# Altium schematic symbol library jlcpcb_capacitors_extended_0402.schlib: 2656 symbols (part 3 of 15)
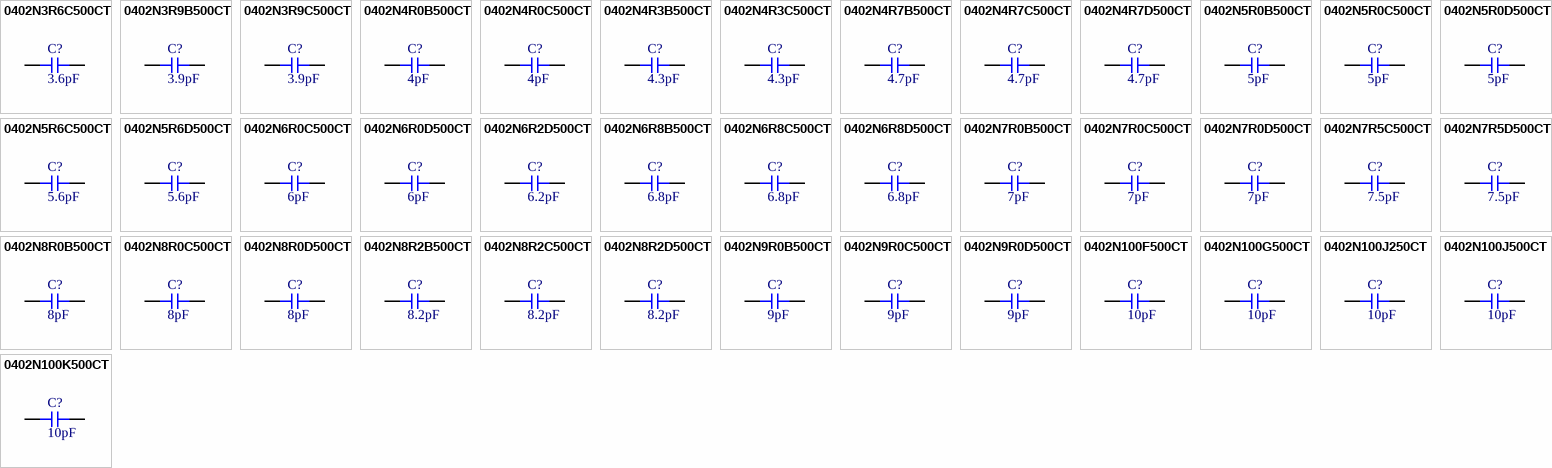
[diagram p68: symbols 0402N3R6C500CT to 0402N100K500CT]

## 0402N100J250CT
designator C?  Capacitance: 10pF  (hidden comment: *)
Capacitor, Ceramic (MLCC), 10pF, ±5%, 25V, NP0, ±5%, SMD 0402; Manufacturer: Walsin Tech Corp; Manufacturer Part Number: 0402N100J250CT
footprint CAP-0402 (0402 (1005M) Capacitor)
pins: 1, 2

## 0402N100J500CT
designator C?  Capacitance: 10pF  (hidden comment: *)
Capacitor, Ceramic (MLCC), 10pF, ±5%, 50V, NP0, ±5%, SMD 0402; Manufacturer: Walsin Tech Corp; Manufacturer Part Number: 0402N100J500CT
footprint CAP-0402 (0402 (1005M) Capacitor)
pins: 1, 2

## 0402N100K500CT
designator C?  Capacitance: 10pF  (hidden comment: *)
Capacitor, Ceramic (MLCC), 10pF, ±10%, 50V, NP0, ±10%, SMD 0402; Manufacturer: Walsin Tech Corp; Manufacturer Part Number: 0402N100K500CT
footprint CAP-0402 (0402 (1005M) Capacitor)
pins: 1, 2

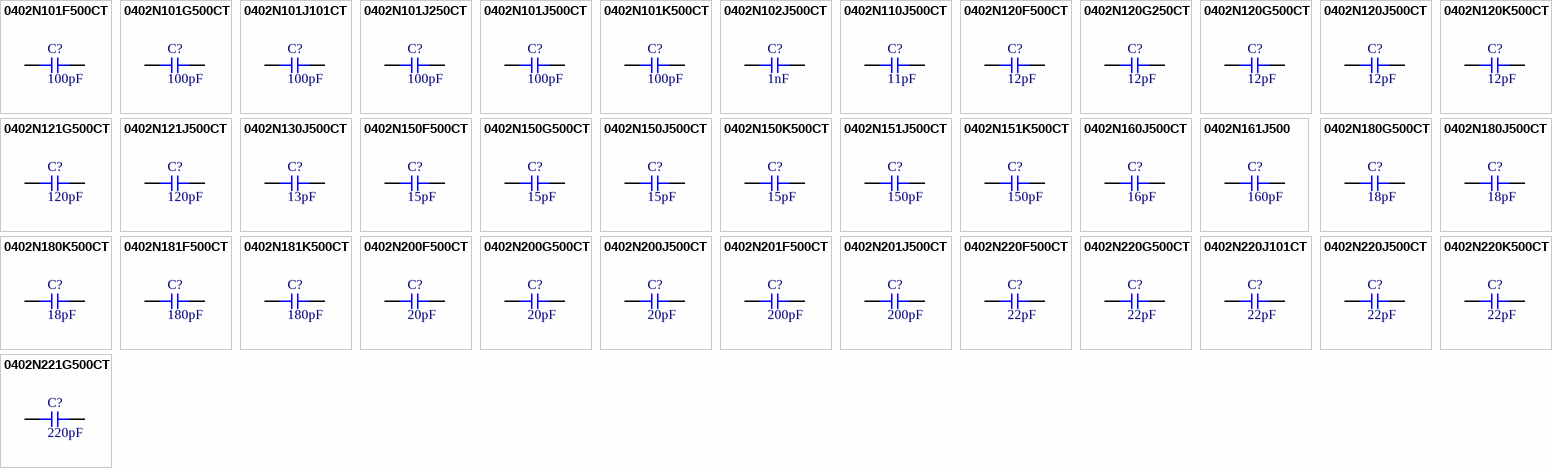
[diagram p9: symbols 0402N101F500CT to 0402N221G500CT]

## 0402N101F500CT
designator C?  Capacitance: 100pF  (hidden comment: *)
Capacitor, Ceramic (MLCC), 100pF, ±1%, 50V, NP0, ±1%, SMD 0402; Manufacturer: Walsin Tech Corp; Manufacturer Part Number: 0402N101F500CT
footprint CAP-0402 (0402 (1005M) Capacitor)
pins: 1, 2

## 0402N101G500CT
designator C?  Capacitance: 100pF  (hidden comment: *)
Capacitor, Ceramic (MLCC), 100pF, ±2%, 50V, NP0, ±2%, SMD 0402; Manufacturer: Walsin Tech Corp; Manufacturer Part Number: 0402N101G500CT
footprint CAP-0402 (0402 (1005M) Capacitor)
pins: 1, 2

## 0402N101J101CT
designator C?  Capacitance: 100pF  (hidden comment: *)
Capacitor, Ceramic (MLCC), 100pF, ±5%, 100V, NP0, ±5%, SMD 0402; Manufacturer: Walsin Tech Corp; Manufacturer Part Number: 0402N101J101CT
footprint CAP-0402 (0402 (1005M) Capacitor)
pins: 1, 2

## 0402N101J250CT
designator C?  Capacitance: 100pF  (hidden comment: *)
Capacitor, Ceramic (MLCC), 100pF, ±5%, 25V, NP0, ±5%, SMD 0402; Manufacturer: Walsin Tech Corp; Manufacturer Part Number: 0402N101J250CT
footprint CAP-0402 (0402 (1005M) Capacitor)
pins: 1, 2

## 0402N101J500CT
designator C?  Capacitance: 100pF  (hidden comment: *)
Capacitor, Ceramic (MLCC), 100pF, ±5%, 50V, NP0, ±5%, SMD 0402; Manufacturer: Walsin Tech Corp; Manufacturer Part Number: 0402N101J500CT
footprint CAP-0402 (0402 (1005M) Capacitor)
pins: 1, 2

## 0402N101K500CT
designator C?  Capacitance: 100pF  (hidden comment: *)
Capacitor, Ceramic (MLCC), 100pF, ±10%, 50V, NP0, ±10%, SMD 0402; Manufacturer: Walsin Tech Corp; Manufacturer Part Number: 0402N101K500CT
footprint CAP-0402 (0402 (1005M) Capacitor)
pins: 1, 2

## 0402N102J500CT
designator C?  Capacitance: 1nF  (hidden comment: *)
Capacitor, Ceramic (MLCC), 1nF, ±5%, 50V, NP0, ±5%, SMD 0402; Manufacturer: Walsin Tech Corp; Manufacturer Part Number: 0402N102J500CT
footprint CAP-0402 (0402 (1005M) Capacitor)
pins: 1, 2

## 0402N110J500CT
designator C?  Capacitance: 11pF  (hidden comment: *)
Capacitor, Ceramic (MLCC), 11pF, ±5%, 50V, NP0, ±5%, SMD 0402; Manufacturer: Walsin Tech Corp; Manufacturer Part Number: 0402N110J500CT
footprint CAP-0402 (0402 (1005M) Capacitor)
pins: 1, 2

## 0402N120F500CT
designator C?  Capacitance: 12pF  (hidden comment: *)
Capacitor, Ceramic (MLCC), 12pF, ±1%, 50V, NP0, ±1%, SMD 0402; Manufacturer: Walsin Tech Corp; Manufacturer Part Number: 0402N120F500CT
footprint CAP-0402 (0402 (1005M) Capacitor)
pins: 1, 2

## 0402N120G250CT
designator C?  Capacitance: 12pF  (hidden comment: *)
Capacitor, Ceramic (MLCC), 12pF, ±2%, 25V, NP0, ±2%, SMD 0402; Manufacturer: Walsin Tech Corp; Manufacturer Part Number: 0402N120G250CT
footprint CAP-0402 (0402 (1005M) Capacitor)
pins: 1, 2

## 0402N120G500CT
designator C?  Capacitance: 12pF  (hidden comment: *)
Capacitor, Ceramic (MLCC), 12pF, ±2%, 50V, NP0, ±2%, SMD 0402; Manufacturer: Walsin Tech Corp; Manufacturer Part Number: 0402N120G500CT
footprint CAP-0402 (0402 (1005M) Capacitor)
pins: 1, 2

## 0402N120J500CT
designator C?  Capacitance: 12pF  (hidden comment: *)
Capacitor, Ceramic (MLCC), 12pF, ±5%, 50V, NP0, ±5%, SMD 0402; Manufacturer: Walsin Tech Corp; Manufacturer Part Number: 0402N120J500CT
footprint CAP-0402 (0402 (1005M) Capacitor)
pins: 1, 2

## 0402N120K500CT
designator C?  Capacitance: 12pF  (hidden comment: *)
Capacitor, Ceramic (MLCC), 12pF, ±10%, 50V, NP0, ±10%, SMD 0402; Manufacturer: Walsin Tech Corp; Manufacturer Part Number: 0402N120K500CT
footprint CAP-0402 (0402 (1005M) Capacitor)
pins: 1, 2

## 0402N121G500CT
designator C?  Capacitance: 120pF  (hidden comment: *)
Capacitor, Ceramic (MLCC), 120pF, ±2%, 50V, NP0, ±2%, SMD 0402; Manufacturer: Walsin Tech Corp; Manufacturer Part Number: 0402N121G500CT
footprint CAP-0402 (0402 (1005M) Capacitor)
pins: 1, 2

## 0402N121J500CT
designator C?  Capacitance: 120pF  (hidden comment: *)
Capacitor, Ceramic (MLCC), 120pF, ±5%, 50V, NP0, ±5%, SMD 0402; Manufacturer: Walsin Tech Corp; Manufacturer Part Number: 0402N121J500CT
footprint CAP-0402 (0402 (1005M) Capacitor)
pins: 1, 2

## 0402N130J500CT
designator C?  Capacitance: 13pF  (hidden comment: *)
Capacitor, Ceramic (MLCC), 13pF, ±5%, 50V, NP0, ±5%, SMD 0402; Manufacturer: Walsin Tech Corp; Manufacturer Part Number: 0402N130J500CT
footprint CAP-0402 (0402 (1005M) Capacitor)
pins: 1, 2

## 0402N150F500CT
designator C?  Capacitance: 15pF  (hidden comment: *)
Capacitor, Ceramic (MLCC), 15pF, ±1%, 50V, NP0, ±1%, SMD 0402; Manufacturer: Walsin Tech Corp; Manufacturer Part Number: 0402N150F500CT
footprint CAP-0402 (0402 (1005M) Capacitor)
pins: 1, 2

## 0402N150G500CT
designator C?  Capacitance: 15pF  (hidden comment: *)
Capacitor, Ceramic (MLCC), 15pF, ±2%, 50V, NP0, ±2%, SMD 0402; Manufacturer: Walsin Tech Corp; Manufacturer Part Number: 0402N150G500CT
footprint CAP-0402 (0402 (1005M) Capacitor)
pins: 1, 2

## 0402N150J500CT
designator C?  Capacitance: 15pF  (hidden comment: *)
Capacitor, Ceramic (MLCC), 15pF, ±5%, 50V, NP0, ±5%, SMD 0402; Manufacturer: Walsin Tech Corp; Manufacturer Part Number: 0402N150J500CT
footprint CAP-0402 (0402 (1005M) Capacitor)
pins: 1, 2

## 0402N150K500CT
designator C?  Capacitance: 15pF  (hidden comment: *)
Capacitor, Ceramic (MLCC), 15pF, ±10%, 50V, NP0, ±10%, SMD 0402; Manufacturer: Walsin Tech Corp; Manufacturer Part Number: 0402N150K500CT
footprint CAP-0402 (0402 (1005M) Capacitor)
pins: 1, 2

## 0402N151J500CT
designator C?  Capacitance: 150pF  (hidden comment: *)
Capacitor, Ceramic (MLCC), 150pF, ±5%, 50V, NP0, ±5%, SMD 0402; Manufacturer: Walsin Tech Corp; Manufacturer Part Number: 0402N151J500CT
footprint CAP-0402 (0402 (1005M) Capacitor)
pins: 1, 2

## 0402N151K500CT
designator C?  Capacitance: 150pF  (hidden comment: *)
Capacitor, Ceramic (MLCC), 150pF, ±10%, 50V, NP0, ±10%, SMD 0402; Manufacturer: Walsin Tech Corp; Manufacturer Part Number: 0402N151K500CT
footprint CAP-0402 (0402 (1005M) Capacitor)
pins: 1, 2

## 0402N160J500CT
designator C?  Capacitance: 16pF  (hidden comment: *)
Capacitor, Ceramic (MLCC), 16pF, ±5%, 50V, NP0, ±5%, SMD 0402; Manufacturer: Walsin Tech Corp; Manufacturer Part Number: 0402N160J500CT
footprint CAP-0402 (0402 (1005M) Capacitor)
pins: 1, 2

## 0402N161J500
designator C?  Capacitance: 160pF  (hidden comment: *)
Capacitor, Ceramic (MLCC), 160pF, ±5%, 50V, NP0, ±5%, SMD 0402; Manufacturer: Walsin Tech Corp; Manufacturer Part Number: 0402N161J500
footprint CAP-0402 (0402 (1005M) Capacitor)
pins: 1, 2

## 0402N180G500CT
designator C?  Capacitance: 18pF  (hidden comment: *)
Capacitor, Ceramic (MLCC), 18pF, ±2%, 50V, NP0, ±2%, SMD 0402; Manufacturer: Walsin Tech Corp; Manufacturer Part Number: 0402N180G500CT
footprint CAP-0402 (0402 (1005M) Capacitor)
pins: 1, 2

## 0402N180J500CT
designator C?  Capacitance: 18pF  (hidden comment: *)
Capacitor, Ceramic (MLCC), 18pF, ±5%, 50V, NP0, ±5%, SMD 0402; Manufacturer: Walsin Tech Corp; Manufacturer Part Number: 0402N180J500CT
footprint CAP-0402 (0402 (1005M) Capacitor)
pins: 1, 2

## 0402N180K500CT
designator C?  Capacitance: 18pF  (hidden comment: *)
Capacitor, Ceramic (MLCC), 18pF, ±10%, 50V, NP0, ±10%, SMD 0402; Manufacturer: Walsin Tech Corp; Manufacturer Part Number: 0402N180K500CT
footprint CAP-0402 (0402 (1005M) Capacitor)
pins: 1, 2

## 0402N181F500CT
designator C?  Capacitance: 180pF  (hidden comment: *)
Capacitor, Ceramic (MLCC), 180pF, ±1%, 50V, NP0, ±1%, SMD 0402; Manufacturer: Walsin Tech Corp; Manufacturer Part Number: 0402N181F500CT
footprint CAP-0402 (0402 (1005M) Capacitor)
pins: 1, 2

## 0402N181K500CT
designator C?  Capacitance: 180pF  (hidden comment: *)
Capacitor, Ceramic (MLCC), 180pF, ±10%, 50V, NP0, ±10%, SMD 0402; Manufacturer: Walsin Tech Corp; Manufacturer Part Number: 0402N181K500CT
footprint CAP-0402 (0402 (1005M) Capacitor)
pins: 1, 2

## 0402N200F500CT
designator C?  Capacitance: 20pF  (hidden comment: *)
Capacitor, Ceramic (MLCC), 20pF, ±1%, 50V, NP0, ±1%, SMD 0402; Manufacturer: Walsin Tech Corp; Manufacturer Part Number: 0402N200F500CT
footprint CAP-0402 (0402 (1005M) Capacitor)
pins: 1, 2

## 0402N200G500CT
designator C?  Capacitance: 20pF  (hidden comment: *)
Capacitor, Ceramic (MLCC), 20pF, ±2%, 50V, NP0, ±2%, SMD 0402; Manufacturer: Walsin Tech Corp; Manufacturer Part Number: 0402N200G500CT
footprint CAP-0402 (0402 (1005M) Capacitor)
pins: 1, 2

## 0402N200J500CT
designator C?  Capacitance: 20pF  (hidden comment: *)
Capacitor, Ceramic (MLCC), 20pF, ±5%, 50V, NP0, ±5%, SMD 0402; Manufacturer: Walsin Tech Corp; Manufacturer Part Number: 0402N200J500CT
footprint CAP-0402 (0402 (1005M) Capacitor)
pins: 1, 2

## 0402N201F500CT
designator C?  Capacitance: 200pF  (hidden comment: *)
Capacitor, Ceramic (MLCC), 200pF, ±1%, 50V, NP0, ±1%, SMD 0402; Manufacturer: Walsin Tech Corp; Manufacturer Part Number: 0402N201F500CT
footprint CAP-0402 (0402 (1005M) Capacitor)
pins: 1, 2

## 0402N201J500CT
designator C?  Capacitance: 200pF  (hidden comment: *)
Capacitor, Ceramic (MLCC), 200pF, ±5%, 50V, NP0, ±5%, SMD 0402; Manufacturer: Walsin Tech Corp; Manufacturer Part Number: 0402N201J500CT
footprint CAP-0402 (0402 (1005M) Capacitor)
pins: 1, 2

## 0402N220F500CT
designator C?  Capacitance: 22pF  (hidden comment: *)
Capacitor, Ceramic (MLCC), 22pF, ±1%, 50V, NP0, ±1%, SMD 0402; Manufacturer: Walsin Tech Corp; Manufacturer Part Number: 0402N220F500CT
footprint CAP-0402 (0402 (1005M) Capacitor)
pins: 1, 2

## 0402N220G500CT
designator C?  Capacitance: 22pF  (hidden comment: *)
Capacitor, Ceramic (MLCC), 22pF, ±2%, 50V, NP0, ±2%, SMD 0402; Manufacturer: Walsin Tech Corp; Manufacturer Part Number: 0402N220G500CT
footprint CAP-0402 (0402 (1005M) Capacitor)
pins: 1, 2

## 0402N220J101CT
designator C?  Capacitance: 22pF  (hidden comment: *)
Capacitor, Ceramic (MLCC), 22pF, ±5%, 100V, NP0, ±5%, SMD 0402; Manufacturer: Walsin Tech Corp; Manufacturer Part Number: 0402N220J101CT
footprint CAP-0402 (0402 (1005M) Capacitor)
pins: 1, 2

## 0402N220J500CT
designator C?  Capacitance: 22pF  (hidden comment: *)
Capacitor, Ceramic (MLCC), 22pF, ±5%, 50V, NP0, ±5%, SMD 0402; Manufacturer: Walsin Tech Corp; Manufacturer Part Number: 0402N220J500CT
footprint CAP-0402 (0402 (1005M) Capacitor)
pins: 1, 2

## 0402N220K500CT
designator C?  Capacitance: 22pF  (hidden comment: *)
Capacitor, Ceramic (MLCC), 22pF, ±10%, 50V, NP0, ±10%, SMD 0402; Manufacturer: Walsin Tech Corp; Manufacturer Part Number: 0402N220K500CT
footprint CAP-0402 (0402 (1005M) Capacitor)
pins: 1, 2

## 0402N221G500CT
designator C?  Capacitance: 220pF  (hidden comment: *)
Capacitor, Ceramic (MLCC), 220pF, ±2%, 50V, NP0, ±2%, SMD 0402; Manufacturer: Walsin Tech Corp; Manufacturer Part Number: 0402N221G500CT
footprint CAP-0402 (0402 (1005M) Capacitor)
pins: 1, 2

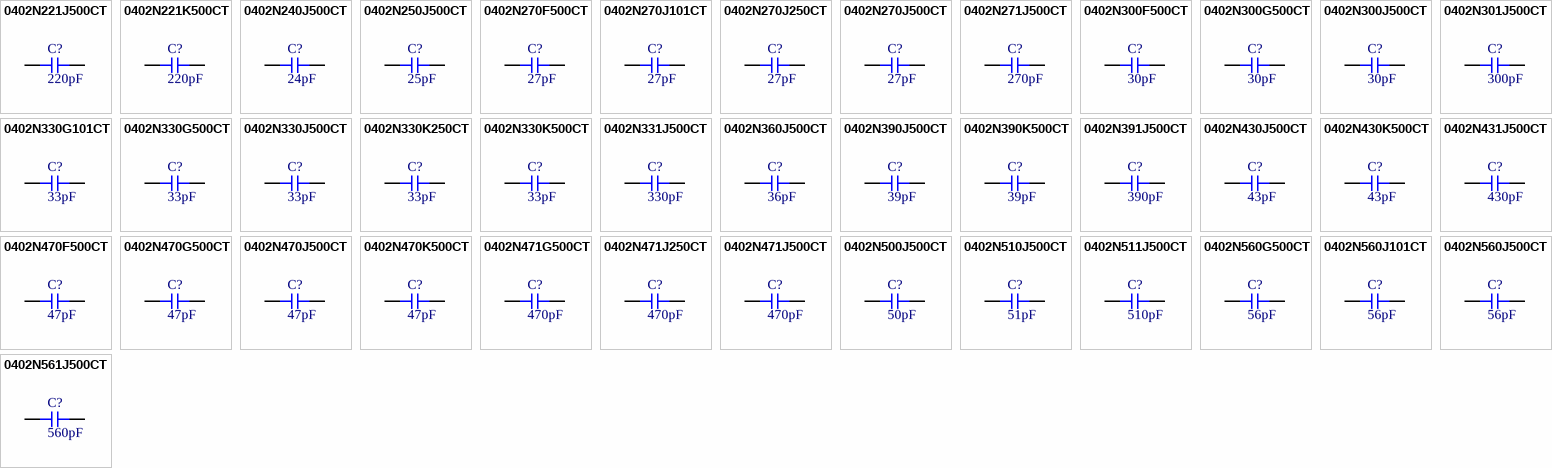
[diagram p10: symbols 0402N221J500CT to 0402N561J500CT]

## 0402N221J500CT
designator C?  Capacitance: 220pF  (hidden comment: *)
Capacitor, Ceramic (MLCC), 220pF, ±5%, 50V, NP0, ±5%, SMD 0402; Manufacturer: Walsin Tech Corp; Manufacturer Part Number: 0402N221J500CT
footprint CAP-0402 (0402 (1005M) Capacitor)
pins: 1, 2

## 0402N221K500CT
designator C?  Capacitance: 220pF  (hidden comment: *)
Capacitor, Ceramic (MLCC), 220pF, ±10%, 50V, NP0, ±10%, SMD 0402; Manufacturer: Walsin Tech Corp; Manufacturer Part Number: 0402N221K500CT
footprint CAP-0402 (0402 (1005M) Capacitor)
pins: 1, 2

## 0402N240J500CT
designator C?  Capacitance: 24pF  (hidden comment: *)
Capacitor, Ceramic (MLCC), 24pF, ±5%, 50V, NP0, ±5%, SMD 0402; Manufacturer: Walsin Tech Corp; Manufacturer Part Number: 0402N240J500CT
footprint CAP-0402 (0402 (1005M) Capacitor)
pins: 1, 2

## 0402N250J500CT
designator C?  Capacitance: 25pF  (hidden comment: *)
Capacitor, Ceramic (MLCC), 25pF, ±5%, 50V, NP0, ±5%, SMD 0402; Manufacturer: Walsin Tech Corp; Manufacturer Part Number: 0402N250J500CT
footprint CAP-0402 (0402 (1005M) Capacitor)
pins: 1, 2

## 0402N270F500CT
designator C?  Capacitance: 27pF  (hidden comment: *)
Capacitor, Ceramic (MLCC), 27pF, ±1%, 50V, NP0, ±1%, SMD 0402; Manufacturer: Walsin Tech Corp; Manufacturer Part Number: 0402N270F500CT
footprint CAP-0402 (0402 (1005M) Capacitor)
pins: 1, 2

## 0402N270J101CT
designator C?  Capacitance: 27pF  (hidden comment: *)
Capacitor, Ceramic (MLCC), 27pF, ±5%, 100V, NP0, ±5%, SMD 0402; Manufacturer: Walsin Tech Corp; Manufacturer Part Number: 0402N270J101CT
footprint CAP-0402 (0402 (1005M) Capacitor)
pins: 1, 2

## 0402N270J250CT
designator C?  Capacitance: 27pF  (hidden comment: *)
Capacitor, Ceramic (MLCC), 27pF, ±5%, 25V, NP0, ±5%, SMD 0402; Manufacturer: Walsin Tech Corp; Manufacturer Part Number: 0402N270J250CT
footprint CAP-0402 (0402 (1005M) Capacitor)
pins: 1, 2

## 0402N270J500CT
designator C?  Capacitance: 27pF  (hidden comment: *)
Capacitor, Ceramic (MLCC), 27pF, ±5%, 50V, NP0, ±5%, SMD 0402; Manufacturer: Walsin Tech Corp; Manufacturer Part Number: 0402N270J500CT
footprint CAP-0402 (0402 (1005M) Capacitor)
pins: 1, 2

## 0402N271J500CT
designator C?  Capacitance: 270pF  (hidden comment: *)
Capacitor, Ceramic (MLCC), 270pF, ±5%, 50V, NP0, ±5%, SMD 0402; Manufacturer: Walsin Tech Corp; Manufacturer Part Number: 0402N271J500CT
footprint CAP-0402 (0402 (1005M) Capacitor)
pins: 1, 2

## 0402N300F500CT
designator C?  Capacitance: 30pF  (hidden comment: *)
Capacitor, Ceramic (MLCC), 30pF, ±1%, 50V, NP0, ±1%, SMD 0402; Manufacturer: Walsin Tech Corp; Manufacturer Part Number: 0402N300F500CT
footprint CAP-0402 (0402 (1005M) Capacitor)
pins: 1, 2

## 0402N300G500CT
designator C?  Capacitance: 30pF  (hidden comment: *)
Capacitor, Ceramic (MLCC), 30pF, ±2%, 50V, NP0, ±2%, SMD 0402; Manufacturer: Walsin Tech Corp; Manufacturer Part Number: 0402N300G500CT
footprint CAP-0402 (0402 (1005M) Capacitor)
pins: 1, 2

## 0402N300J500CT
designator C?  Capacitance: 30pF  (hidden comment: *)
Capacitor, Ceramic (MLCC), 30pF, ±5%, 50V, NP0, ±5%, SMD 0402; Manufacturer: Walsin Tech Corp; Manufacturer Part Number: 0402N300J500CT
footprint CAP-0402 (0402 (1005M) Capacitor)
pins: 1, 2

## 0402N301J500CT
designator C?  Capacitance: 300pF  (hidden comment: *)
Capacitor, Ceramic (MLCC), 300pF, ±5%, 50V, NP0, ±5%, SMD 0402; Manufacturer: Walsin Tech Corp; Manufacturer Part Number: 0402N301J500CT
footprint CAP-0402 (0402 (1005M) Capacitor)
pins: 1, 2

## 0402N330G101CT
designator C?  Capacitance: 33pF  (hidden comment: *)
Capacitor, Ceramic (MLCC), 33pF, ±2%, 100V, NP0, ±2%, SMD 0402; Manufacturer: Walsin Tech Corp; Manufacturer Part Number: 0402N330G101CT
footprint CAP-0402 (0402 (1005M) Capacitor)
pins: 1, 2

## 0402N330G500CT
designator C?  Capacitance: 33pF  (hidden comment: *)
Capacitor, Ceramic (MLCC), 33pF, ±2%, 50V, NP0, ±2%, SMD 0402; Manufacturer: Walsin Tech Corp; Manufacturer Part Number: 0402N330G500CT
footprint CAP-0402 (0402 (1005M) Capacitor)
pins: 1, 2

## 0402N330J500CT
designator C?  Capacitance: 33pF  (hidden comment: *)
Capacitor, Ceramic (MLCC), 33pF, ±5%, 50V, NP0, ±5%, SMD 0402; Manufacturer: Walsin Tech Corp; Manufacturer Part Number: 0402N330J500CT
footprint CAP-0402 (0402 (1005M) Capacitor)
pins: 1, 2

## 0402N330K250CT
designator C?  Capacitance: 33pF  (hidden comment: *)
Capacitor, Ceramic (MLCC), 33pF, ±10%, 25V, NP0, ±10%, SMD 0402; Manufacturer: Walsin Tech Corp; Manufacturer Part Number: 0402N330K250CT
footprint CAP-0402 (0402 (1005M) Capacitor)
pins: 1, 2

## 0402N330K500CT
designator C?  Capacitance: 33pF  (hidden comment: *)
Capacitor, Ceramic (MLCC), 33pF, ±10%, 50V, NP0, ±10%, SMD 0402; Manufacturer: Walsin Tech Corp; Manufacturer Part Number: 0402N330K500CT
footprint CAP-0402 (0402 (1005M) Capacitor)
pins: 1, 2

## 0402N331J500CT
designator C?  Capacitance: 330pF  (hidden comment: *)
Capacitor, Ceramic (MLCC), 330pF, ±5%, 50V, NP0, ±5%, SMD 0402; Manufacturer: Walsin Tech Corp; Manufacturer Part Number: 0402N331J500CT
footprint CAP-0402 (0402 (1005M) Capacitor)
pins: 1, 2

## 0402N360J500CT
designator C?  Capacitance: 36pF  (hidden comment: *)
Capacitor, Ceramic (MLCC), 36pF, ±5%, 50V, NP0, ±5%, SMD 0402; Manufacturer: Walsin Tech Corp; Manufacturer Part Number: 0402N360J500CT
footprint CAP-0402 (0402 (1005M) Capacitor)
pins: 1, 2

## 0402N390J500CT
designator C?  Capacitance: 39pF  (hidden comment: *)
Capacitor, Ceramic (MLCC), 39pF, ±5%, 50V, NP0, ±5%, SMD 0402; Manufacturer: Walsin Tech Corp; Manufacturer Part Number: 0402N390J500CT
footprint CAP-0402 (0402 (1005M) Capacitor)
pins: 1, 2

## 0402N390K500CT
designator C?  Capacitance: 39pF  (hidden comment: *)
Capacitor, Ceramic (MLCC), 39pF, ±10%, 50V, NP0, ±10%, SMD 0402; Manufacturer: Walsin Tech Corp; Manufacturer Part Number: 0402N390K500CT
footprint CAP-0402 (0402 (1005M) Capacitor)
pins: 1, 2

## 0402N391J500CT
designator C?  Capacitance: 390pF  (hidden comment: *)
Capacitor, Ceramic (MLCC), 390pF, ±5%, 50V, NP0, ±5%, SMD 0402; Manufacturer: Walsin Tech Corp; Manufacturer Part Number: 0402N391J500CT
footprint CAP-0402 (0402 (1005M) Capacitor)
pins: 1, 2

## 0402N430J500CT
designator C?  Capacitance: 43pF  (hidden comment: *)
Capacitor, Ceramic (MLCC), 43pF, ±5%, 50V, NP0, ±5%, SMD 0402; Manufacturer: Walsin Tech Corp; Manufacturer Part Number: 0402N430J500CT
footprint CAP-0402 (0402 (1005M) Capacitor)
pins: 1, 2

## 0402N430K500CT
designator C?  Capacitance: 43pF  (hidden comment: *)
Capacitor, Ceramic (MLCC), 43pF, ±10%, 50V, NP0, ±10%, SMD 0402; Manufacturer: Walsin Tech Corp; Manufacturer Part Number: 0402N430K500CT
footprint CAP-0402 (0402 (1005M) Capacitor)
pins: 1, 2

## 0402N431J500CT
designator C?  Capacitance: 430pF  (hidden comment: *)
Capacitor, Ceramic (MLCC), 430pF, ±5%, 50V, NP0, ±5%, SMD 0402; Manufacturer: Walsin Tech Corp; Manufacturer Part Number: 0402N431J500CT
footprint CAP-0402 (0402 (1005M) Capacitor)
pins: 1, 2

## 0402N470F500CT
designator C?  Capacitance: 47pF  (hidden comment: *)
Capacitor, Ceramic (MLCC), 47pF, ±1%, 50V, NP0, ±1%, SMD 0402; Manufacturer: Walsin Tech Corp; Manufacturer Part Number: 0402N470F500CT
footprint CAP-0402 (0402 (1005M) Capacitor)
pins: 1, 2

## 0402N470G500CT
designator C?  Capacitance: 47pF  (hidden comment: *)
Capacitor, Ceramic (MLCC), 47pF, ±2%, 50V, NP0, ±2%, SMD 0402; Manufacturer: Walsin Tech Corp; Manufacturer Part Number: 0402N470G500CT
footprint CAP-0402 (0402 (1005M) Capacitor)
pins: 1, 2

## 0402N470J500CT
designator C?  Capacitance: 47pF  (hidden comment: *)
Capacitor, Ceramic (MLCC), 47pF, ±5%, 50V, NP0, ±5%, SMD 0402; Manufacturer: Walsin Tech Corp; Manufacturer Part Number: 0402N470J500CT
footprint CAP-0402 (0402 (1005M) Capacitor)
pins: 1, 2

## 0402N470K500CT
designator C?  Capacitance: 47pF  (hidden comment: *)
Capacitor, Ceramic (MLCC), 47pF, ±10%, 50V, NP0, ±10%, SMD 0402; Manufacturer: Walsin Tech Corp; Manufacturer Part Number: 0402N470K500CT
footprint CAP-0402 (0402 (1005M) Capacitor)
pins: 1, 2

## 0402N471G500CT
designator C?  Capacitance: 470pF  (hidden comment: *)
Capacitor, Ceramic (MLCC), 470pF, ±2%, 50V, NP0, ±2%, SMD 0402; Manufacturer: Walsin Tech Corp; Manufacturer Part Number: 0402N471G500CT
footprint CAP-0402 (0402 (1005M) Capacitor)
pins: 1, 2

## 0402N471J250CT
designator C?  Capacitance: 470pF  (hidden comment: *)
Capacitor, Ceramic (MLCC), 470pF, ±5%, 25V, NP0, ±5%, SMD 0402; Manufacturer: Walsin Tech Corp; Manufacturer Part Number: 0402N471J250CT
footprint CAP-0402 (0402 (1005M) Capacitor)
pins: 1, 2

## 0402N471J500CT
designator C?  Capacitance: 470pF  (hidden comment: *)
Capacitor, Ceramic (MLCC), 470pF, ±5%, 50V, NP0, ±5%, SMD 0402; Manufacturer: Walsin Tech Corp; Manufacturer Part Number: 0402N471J500CT
footprint CAP-0402 (0402 (1005M) Capacitor)
pins: 1, 2

## 0402N500J500CT
designator C?  Capacitance: 50pF  (hidden comment: *)
Capacitor, Ceramic (MLCC), 50pF, ±5%, 50V, NP0, ±5%, SMD 0402; Manufacturer: Walsin Tech Corp; Manufacturer Part Number: 0402N500J500CT
footprint CAP-0402 (0402 (1005M) Capacitor)
pins: 1, 2

## 0402N510J500CT
designator C?  Capacitance: 51pF  (hidden comment: *)
Capacitor, Ceramic (MLCC), 51pF, ±5%, 50V, NP0, ±5%, SMD 0402; Manufacturer: Walsin Tech Corp; Manufacturer Part Number: 0402N510J500CT
footprint CAP-0402 (0402 (1005M) Capacitor)
pins: 1, 2

## 0402N511J500CT
designator C?  Capacitance: 510pF  (hidden comment: *)
Capacitor, Ceramic (MLCC), 510pF, ±5%, 50V, NP0, ±5%, SMD 0402; Manufacturer: Walsin Tech Corp; Manufacturer Part Number: 0402N511J500CT
footprint CAP-0402 (0402 (1005M) Capacitor)
pins: 1, 2

## 0402N560G500CT
designator C?  Capacitance: 56pF  (hidden comment: *)
Capacitor, Ceramic (MLCC), 56pF, ±2%, 50V, NP0, ±2%, SMD 0402; Manufacturer: Walsin Tech Corp; Manufacturer Part Number: 0402N560G500CT
footprint CAP-0402 (0402 (1005M) Capacitor)
pins: 1, 2

## 0402N560J101CT
designator C?  Capacitance: 56pF  (hidden comment: *)
Capacitor, Ceramic (MLCC), 56pF, ±5%, 100V, NP0, ±5%, SMD 0402; Manufacturer: Walsin Tech Corp; Manufacturer Part Number: 0402N560J101CT
footprint CAP-0402 (0402 (1005M) Capacitor)
pins: 1, 2

## 0402N560J500CT
designator C?  Capacitance: 56pF  (hidden comment: *)
Capacitor, Ceramic (MLCC), 56pF, ±5%, 50V, NP0, ±5%, SMD 0402; Manufacturer: Walsin Tech Corp; Manufacturer Part Number: 0402N560J500CT
footprint CAP-0402 (0402 (1005M) Capacitor)
pins: 1, 2

## 0402N561J500CT
designator C?  Capacitance: 560pF  (hidden comment: *)
Capacitor, Ceramic (MLCC), 560pF, ±5%, 50V, NP0, ±5%, SMD 0402; Manufacturer: Walsin Tech Corp; Manufacturer Part Number: 0402N561J500CT
footprint CAP-0402 (0402 (1005M) Capacitor)
pins: 1, 2

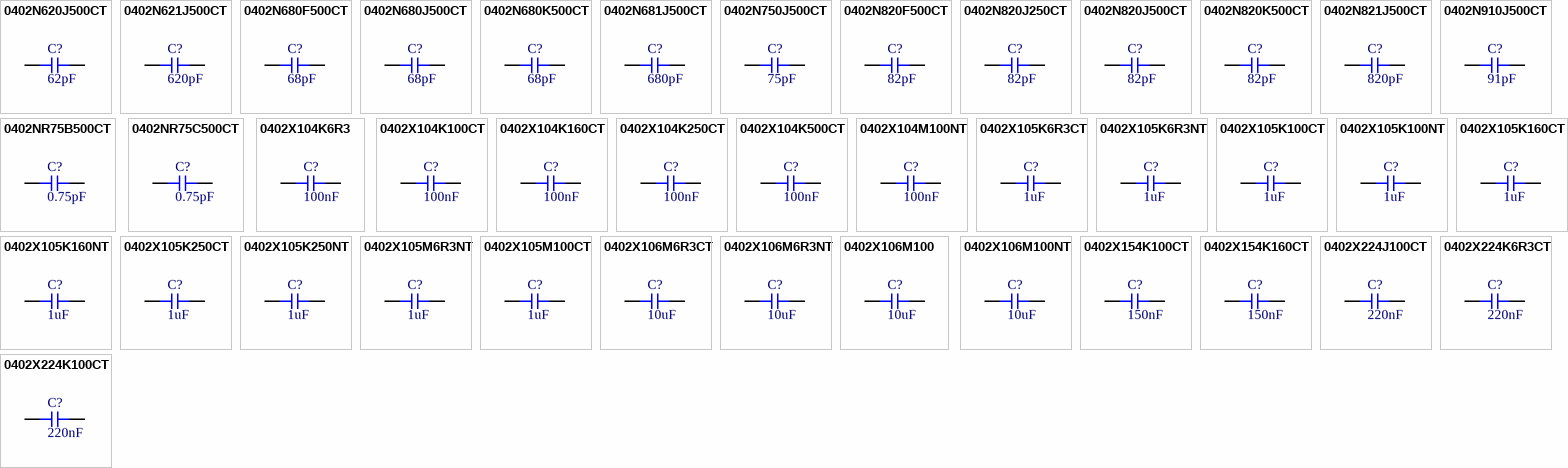
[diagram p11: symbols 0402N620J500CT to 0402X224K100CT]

## 0402N620J500CT
designator C?  Capacitance: 62pF  (hidden comment: *)
Capacitor, Ceramic (MLCC), 62pF, ±5%, 50V, NP0, ±5%, SMD 0402; Manufacturer: Walsin Tech Corp; Manufacturer Part Number: 0402N620J500CT
footprint CAP-0402 (0402 (1005M) Capacitor)
pins: 1, 2

## 0402N621J500CT
designator C?  Capacitance: 620pF  (hidden comment: *)
Capacitor, Ceramic (MLCC), 620pF, ±5%, 50V, NP0, ±5%, SMD 0402; Manufacturer: Walsin Tech Corp; Manufacturer Part Number: 0402N621J500CT
footprint CAP-0402 (0402 (1005M) Capacitor)
pins: 1, 2

## 0402N680F500CT
designator C?  Capacitance: 68pF  (hidden comment: *)
Capacitor, Ceramic (MLCC), 68pF, ±1%, 50V, NP0, ±1%, SMD 0402; Manufacturer: Walsin Tech Corp; Manufacturer Part Number: 0402N680F500CT
footprint CAP-0402 (0402 (1005M) Capacitor)
pins: 1, 2

## 0402N680J500CT
designator C?  Capacitance: 68pF  (hidden comment: *)
Capacitor, Ceramic (MLCC), 68pF, ±5%, 50V, NP0, ±5%, SMD 0402; Manufacturer: Walsin Tech Corp; Manufacturer Part Number: 0402N680J500CT
footprint CAP-0402 (0402 (1005M) Capacitor)
pins: 1, 2

## 0402N680K500CT
designator C?  Capacitance: 68pF  (hidden comment: *)
Capacitor, Ceramic (MLCC), 68pF, ±10%, 50V, NP0, ±10%, SMD 0402; Manufacturer: Walsin Tech Corp; Manufacturer Part Number: 0402N680K500CT
footprint CAP-0402 (0402 (1005M) Capacitor)
pins: 1, 2

## 0402N681J500CT
designator C?  Capacitance: 680pF  (hidden comment: *)
Capacitor, Ceramic (MLCC), 680pF, ±5%, 50V, NP0, ±5%, SMD 0402; Manufacturer: Walsin Tech Corp; Manufacturer Part Number: 0402N681J500CT
footprint CAP-0402 (0402 (1005M) Capacitor)
pins: 1, 2

## 0402N750J500CT
designator C?  Capacitance: 75pF  (hidden comment: *)
Capacitor, Ceramic (MLCC), 75pF, ±5%, 50V, NP0, ±5%, SMD 0402; Manufacturer: Walsin Tech Corp; Manufacturer Part Number: 0402N750J500CT
footprint CAP-0402 (0402 (1005M) Capacitor)
pins: 1, 2

## 0402N820F500CT
designator C?  Capacitance: 82pF  (hidden comment: *)
Capacitor, Ceramic (MLCC), 82pF, ±1%, 50V, NP0, ±1%, SMD 0402; Manufacturer: Walsin Tech Corp; Manufacturer Part Number: 0402N820F500CT
footprint CAP-0402 (0402 (1005M) Capacitor)
pins: 1, 2

## 0402N820J250CT
designator C?  Capacitance: 82pF  (hidden comment: *)
Capacitor, Ceramic (MLCC), 82pF, ±5%, 25V, NP0, ±5%, SMD 0402; Manufacturer: Walsin Tech Corp; Manufacturer Part Number: 0402N820J250CT
footprint CAP-0402 (0402 (1005M) Capacitor)
pins: 1, 2

## 0402N820J500CT
designator C?  Capacitance: 82pF  (hidden comment: *)
Capacitor, Ceramic (MLCC), 82pF, ±5%, 50V, NP0, ±5%, SMD 0402; Manufacturer: Walsin Tech Corp; Manufacturer Part Number: 0402N820J500CT
footprint CAP-0402 (0402 (1005M) Capacitor)
pins: 1, 2

## 0402N820K500CT
designator C?  Capacitance: 82pF  (hidden comment: *)
Capacitor, Ceramic (MLCC), 82pF, ±10%, 50V, NP0, ±10%, SMD 0402; Manufacturer: Walsin Tech Corp; Manufacturer Part Number: 0402N820K500CT
footprint CAP-0402 (0402 (1005M) Capacitor)
pins: 1, 2

## 0402N821J500CT
designator C?  Capacitance: 820pF  (hidden comment: *)
Capacitor, Ceramic (MLCC), 820pF, ±5%, 50V, NP0, ±5%, SMD 0402; Manufacturer: Walsin Tech Corp; Manufacturer Part Number: 0402N821J500CT
footprint CAP-0402 (0402 (1005M) Capacitor)
pins: 1, 2

## 0402N910J500CT
designator C?  Capacitance: 91pF  (hidden comment: *)
Capacitor, Ceramic (MLCC), 91pF, ±5%, 50V, NP0, ±5%, SMD 0402; Manufacturer: Walsin Tech Corp; Manufacturer Part Number: 0402N910J500CT
footprint CAP-0402 (0402 (1005M) Capacitor)
pins: 1, 2

## 0402NR75B500CT
designator C?  Capacitance: 0.75pF  (hidden comment: *)
Capacitor, Ceramic (MLCC), 0.75pF, ±0.1pF, 50V, NP0, ±0.1pF, SMD 0402; Manufacturer: Walsin Tech Corp; Manufacturer Part Number: 0402NR75B500CT
footprint CAP-0402 (0402 (1005M) Capacitor)
pins: 1, 2

## 0402NR75C500CT
designator C?  Capacitance: 0.75pF  (hidden comment: *)
Capacitor, Ceramic (MLCC), 0.75pF, ±0.25pF, 50V, NP0, ±0.25pF, SMD 0402; Manufacturer: Walsin Tech Corp; Manufacturer Part Number: 0402NR75C500CT
footprint CAP-0402 (0402 (1005M) Capacitor)
pins: 1, 2

## 0402X104K6R3
designator C?  Capacitance: 100nF  (hidden comment: *)
Capacitor, Ceramic (MLCC), 100nF, ±10%, 6.3V, X5R, ±10%, SMD 0402; Manufacturer: Walsin Tech Corp; Manufacturer Part Number: 0402X104K6R3
footprint CAP-0402 (0402 (1005M) Capacitor)
pins: 1, 2

## 0402X104K100CT
designator C?  Capacitance: 100nF  (hidden comment: *)
Capacitor, Ceramic (MLCC), 100nF, ±10%, 10V, X5R, ±10%, SMD 0402; Manufacturer: Walsin Tech Corp; Manufacturer Part Number: 0402X104K100CT
footprint CAP-0402 (0402 (1005M) Capacitor)
pins: 1, 2

## 0402X104K160CT
designator C?  Capacitance: 100nF  (hidden comment: *)
Capacitor, Ceramic (MLCC), 100nF, ±10%, 16V, X5R, ±10%, SMD 0402; Manufacturer: Walsin Tech Corp; Manufacturer Part Number: 0402X104K160CT
footprint CAP-0402 (0402 (1005M) Capacitor)
pins: 1, 2

## 0402X104K250CT
designator C?  Capacitance: 100nF  (hidden comment: *)
Capacitor, Ceramic (MLCC), 100nF, ±10%, 25V, X5R, ±10%, SMD 0402; Manufacturer: Walsin Tech Corp; Manufacturer Part Number: 0402X104K250CT
footprint CAP-0402 (0402 (1005M) Capacitor)
pins: 1, 2

## 0402X104K500CT
designator C?  Capacitance: 100nF  (hidden comment: *)
Capacitor, Ceramic (MLCC), 100nF, ±10%, 50V, X5R, ±10%, SMD 0402; Manufacturer: Walsin Tech Corp; Manufacturer Part Number: 0402X104K500CT
footprint CAP-0402 (0402 (1005M) Capacitor)
pins: 1, 2

## 0402X104M100NT
designator C?  Capacitance: 100nF  (hidden comment: *)
Capacitor, Ceramic (MLCC), 100nF, ±20%, 10V, X5R, ±20%, SMD 0402; Manufacturer: FH(Guangdong Fenghua Advanced Tech); Manufacturer Part Number: 0402X104M100NT
footprint CAP-0402 (0402 (1005M) Capacitor)
pins: 1, 2

## 0402X105K6R3CT
designator C?  Capacitance: 1uF  (hidden comment: *)
Capacitor, Ceramic (MLCC), 1uF, ±10%, 6.3V, X5R, ±10%, SMD 0402; Manufacturer: Walsin Tech Corp; Manufacturer Part Number: 0402X105K6R3CT
footprint CAP-0402 (0402 (1005M) Capacitor)
pins: 1, 2

## 0402X105K6R3NT
designator C?  Capacitance: 1uF  (hidden comment: *)
Capacitor, Ceramic (MLCC), 1uF, ±10%, 6.3V, X5R, ±10%, SMD 0402; Manufacturer: FH(Guangdong Fenghua Advanced Tech); Manufacturer Part Number: 0402X105K6R3NT
footprint CAP-0402 (0402 (1005M) Capacitor)
pins: 1, 2

## 0402X105K100CT
designator C?  Capacitance: 1uF  (hidden comment: *)
Capacitor, Ceramic (MLCC), 1uF, ±10%, 10V, X5R, ±10%, SMD 0402; Manufacturer: Walsin Tech Corp; Manufacturer Part Number: 0402X105K100CT
footprint CAP-0402 (0402 (1005M) Capacitor)
pins: 1, 2

## 0402X105K100NT
designator C?  Capacitance: 1uF  (hidden comment: *)
Capacitor, Ceramic (MLCC), 1uF, ±10%, 10V, X5R, ±10%, SMD 0402; Manufacturer: FH(Guangdong Fenghua Advanced Tech); Manufacturer Part Number: 0402X105K100NT
footprint CAP-0402 (0402 (1005M) Capacitor)
pins: 1, 2

## 0402X105K160CT
designator C?  Capacitance: 1uF  (hidden comment: *)
Capacitor, Ceramic (MLCC), 1uF, ±10%, 16V, X5R, ±10%, SMD 0402; Manufacturer: Walsin Tech Corp; Manufacturer Part Number: 0402X105K160CT
footprint CAP-0402 (0402 (1005M) Capacitor)
pins: 1, 2

## 0402X105K160NT
designator C?  Capacitance: 1uF  (hidden comment: *)
Capacitor, Ceramic (MLCC), 1uF, ±10%, 16V, X5R, ±10%, SMD 0402; Manufacturer: FH(Guangdong Fenghua Advanced Tech); Manufacturer Part Number: 0402X105K160NT
footprint CAP-0402 (0402 (1005M) Capacitor)
pins: 1, 2

## 0402X105K250CT
designator C?  Capacitance: 1uF  (hidden comment: *)
Capacitor, Ceramic (MLCC), 1uF, ±10%, 25V, X5R, ±10%, SMD 0402; Manufacturer: Walsin Tech Corp; Manufacturer Part Number: 0402X105K250CT
footprint CAP-0402 (0402 (1005M) Capacitor)
pins: 1, 2

## 0402X105K250NT
designator C?  Capacitance: 1uF  (hidden comment: *)
Capacitor, Ceramic (MLCC), 1uF, ±10%, 25V, ±10%, SMD 0402; Manufacturer: FH(Guangdong Fenghua Advanced Tech); Manufacturer Part Number: 0402X105K250NT
footprint CAP-0402 (0402 (1005M) Capacitor)
pins: 1, 2

## 0402X105M6R3NT
designator C?  Capacitance: 1uF  (hidden comment: *)
Capacitor, Ceramic (MLCC), 1uF, ±20%, 6.3V, X5R, ±20%, SMD 0402; Manufacturer: FH(Guangdong Fenghua Advanced Tech); Manufacturer Part Number: 0402X105M6R3NT
footprint CAP-0402 (0402 (1005M) Capacitor)
pins: 1, 2

## 0402X105M100CT
designator C?  Capacitance: 1uF  (hidden comment: *)
Capacitor, Ceramic (MLCC), 1uF, ±20%, 10V, X5R, ±20%, SMD 0402; Manufacturer: Walsin Tech Corp; Manufacturer Part Number: 0402X105M100CT
footprint CAP-0402 (0402 (1005M) Capacitor)
pins: 1, 2

## 0402X106M6R3CT
designator C?  Capacitance: 10uF  (hidden comment: *)
Capacitor, Ceramic (MLCC), 10uF, ±20%, 6.3V, X5R, ±20%, SMD 0402; Manufacturer: Walsin Tech Corp; Manufacturer Part Number: 0402X106M6R3CT
footprint CAP-0402 (0402 (1005M) Capacitor)
pins: 1, 2

## 0402X106M6R3NT
designator C?  Capacitance: 10uF  (hidden comment: *)
Capacitor, Ceramic (MLCC), 10uF, ±20%, 6.3V, X5R, ±20%, SMD 0402; Manufacturer: FH(Guangdong Fenghua Advanced Tech); Manufacturer Part Number: 0402X106M6R3NT
footprint CAP-0402 (0402 (1005M) Capacitor)
pins: 1, 2

## 0402X106M100
designator C?  Capacitance: 10uF  (hidden comment: *)
Capacitor, Ceramic (MLCC), 10uF, ±20%, 10V, X5R, ±20%, SMD 0402; Manufacturer: Walsin Tech Corp; Manufacturer Part Number: 0402X106M100
footprint CAP-0402 (0402 (1005M) Capacitor)
pins: 1, 2

## 0402X106M100NT
designator C?  Capacitance: 10uF  (hidden comment: *)
Capacitor, Ceramic (MLCC), 10uF, ±20%, 10V, ±20%, SMD 0402; Manufacturer: FH(Guangdong Fenghua Advanced Tech); Manufacturer Part Number: 0402X106M100NT
footprint CAP-0402 (0402 (1005M) Capacitor)
pins: 1, 2

## 0402X154K100CT
designator C?  Capacitance: 150nF  (hidden comment: *)
Capacitor, Ceramic (MLCC), 150nF, ±10%, 10V, X5R, ±10%, SMD 0402; Manufacturer: Walsin Tech Corp; Manufacturer Part Number: 0402X154K100CT
footprint CAP-0402 (0402 (1005M) Capacitor)
pins: 1, 2

## 0402X154K160CT
designator C?  Capacitance: 150nF  (hidden comment: *)
Capacitor, Ceramic (MLCC), 150nF, ±10%, 16V, X5R, ±10%, SMD 0402; Manufacturer: Walsin Tech Corp; Manufacturer Part Number: 0402X154K160CT
footprint CAP-0402 (0402 (1005M) Capacitor)
pins: 1, 2

## 0402X224J100CT
designator C?  Capacitance: 220nF  (hidden comment: *)
Capacitor, Ceramic (MLCC), 220nF, ±5%, 10V, X5R, ±5%, SMD 0402; Manufacturer: Walsin Tech Corp; Manufacturer Part Number: 0402X224J100CT
footprint CAP-0402 (0402 (1005M) Capacitor)
pins: 1, 2

## 0402X224K6R3CT
designator C?  Capacitance: 220nF  (hidden comment: *)
Capacitor, Ceramic (MLCC), 220nF, ±10%, 6.3V, X5R, ±10%, SMD 0402; Manufacturer: Walsin Tech Corp; Manufacturer Part Number: 0402X224K6R3CT
footprint CAP-0402 (0402 (1005M) Capacitor)
pins: 1, 2

## 0402X224K100CT
designator C?  Capacitance: 220nF  (hidden comment: *)
Capacitor, Ceramic (MLCC), 220nF, ±10%, 10V, X5R, ±10%, SMD 0402; Manufacturer: Walsin Tech Corp; Manufacturer Part Number: 0402X224K100CT
footprint CAP-0402 (0402 (1005M) Capacitor)
pins: 1, 2

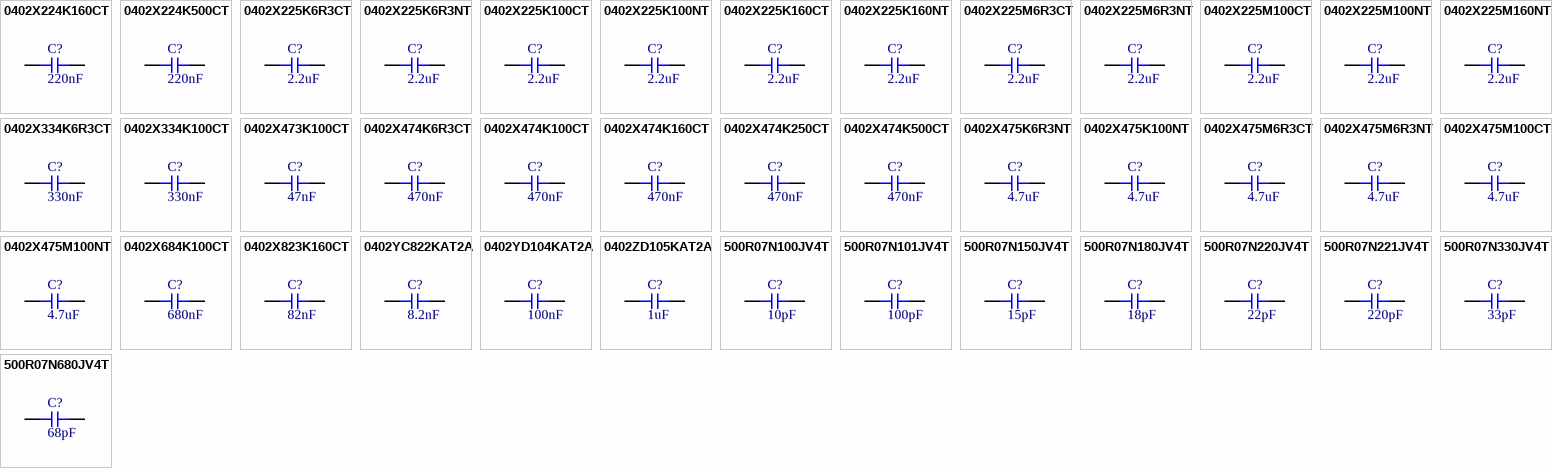
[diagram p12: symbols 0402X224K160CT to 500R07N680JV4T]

## 0402X224K160CT
designator C?  Capacitance: 220nF  (hidden comment: *)
Capacitor, Ceramic (MLCC), 220nF, ±10%, 16V, X5R, ±10%, SMD 0402; Manufacturer: Walsin Tech Corp; Manufacturer Part Number: 0402X224K160CT
footprint CAP-0402 (0402 (1005M) Capacitor)
pins: 1, 2

## 0402X224K500CT
designator C?  Capacitance: 220nF  (hidden comment: *)
Capacitor, Ceramic (MLCC), 220nF, ±10%, 50V, X5R, ±10%, SMD 0402; Manufacturer: Walsin Tech Corp; Manufacturer Part Number: 0402X224K500CT
footprint CAP-0402 (0402 (1005M) Capacitor)
pins: 1, 2

## 0402X225K6R3CT
designator C?  Capacitance: 2.2uF  (hidden comment: *)
Capacitor, Ceramic (MLCC), 2.2uF, ±10%, 6.3V, X5R, ±10%, SMD 0402; Manufacturer: Walsin Tech Corp; Manufacturer Part Number: 0402X225K6R3CT
footprint CAP-0402 (0402 (1005M) Capacitor)
pins: 1, 2

## 0402X225K6R3NT
designator C?  Capacitance: 2.2uF  (hidden comment: *)
Capacitor, Ceramic (MLCC), 2.2uF, ±10%, 6.3V, X5R, ±10%, SMD 0402; Manufacturer: FH(Guangdong Fenghua Advanced Tech); Manufacturer Part Number: 0402X225K6R3NT
footprint CAP-0402 (0402 (1005M) Capacitor)
pins: 1, 2

## 0402X225K100CT
designator C?  Capacitance: 2.2uF  (hidden comment: *)
Capacitor, Ceramic (MLCC), 2.2uF, ±10%, 10V, X5R, ±10%, SMD 0402; Manufacturer: Walsin Tech Corp; Manufacturer Part Number: 0402X225K100CT
footprint CAP-0402 (0402 (1005M) Capacitor)
pins: 1, 2

## 0402X225K100NT
designator C?  Capacitance: 2.2uF  (hidden comment: *)
Capacitor, Ceramic (MLCC), 2.2uF, ±10%, 10V, X5R, ±10%, SMD 0402; Manufacturer: FH(Guangdong Fenghua Advanced Tech); Manufacturer Part Number: 0402X225K100NT
footprint CAP-0402 (0402 (1005M) Capacitor)
pins: 1, 2

## 0402X225K160CT
designator C?  Capacitance: 2.2uF  (hidden comment: *)
Capacitor, Ceramic (MLCC), 2.2uF, ±10%, X5R, ±10%, SMD 0402; Manufacturer: Walsin Tech Corp; Manufacturer Part Number: 0402X225K160CT
footprint CAP-0402 (0402 (1005M) Capacitor)
pins: 1, 2

## 0402X225K160NT
designator C?  Capacitance: 2.2uF  (hidden comment: *)
Capacitor, Ceramic (MLCC), 2.2uF, ±10%, 16V, X5R, ±10%, SMD 0402; Manufacturer: FH(Guangdong Fenghua Advanced Tech); Manufacturer Part Number: 0402X225K160NT
footprint CAP-0402 (0402 (1005M) Capacitor)
pins: 1, 2

## 0402X225M6R3CT
designator C?  Capacitance: 2.2uF  (hidden comment: *)
Capacitor, Ceramic (MLCC), 2.2uF, ±20%, 6.3V, X5R, ±20%, SMD 0402; Manufacturer: Walsin Tech Corp; Manufacturer Part Number: 0402X225M6R3CT
footprint CAP-0402 (0402 (1005M) Capacitor)
pins: 1, 2

## 0402X225M6R3NT
designator C?  Capacitance: 2.2uF  (hidden comment: *)
Capacitor, Ceramic (MLCC), 2.2uF, ±20%, 6.3V, X5R, ±20%, SMD 0402; Manufacturer: FH(Guangdong Fenghua Advanced Tech); Manufacturer Part Number: 0402X225M6R3NT
footprint CAP-0402 (0402 (1005M) Capacitor)
pins: 1, 2

## 0402X225M100CT
designator C?  Capacitance: 2.2uF  (hidden comment: *)
Capacitor, Ceramic (MLCC), 2.2uF, ±20%, 10V, X5R, ±20%, SMD 0402; Manufacturer: Walsin Tech Corp; Manufacturer Part Number: 0402X225M100CT
footprint CAP-0402 (0402 (1005M) Capacitor)
pins: 1, 2

## 0402X225M100NT
designator C?  Capacitance: 2.2uF  (hidden comment: *)
Capacitor, Ceramic (MLCC), 2.2uF, ±20%, 10V, X5R, ±20%, SMD 0402; Manufacturer: FH(Guangdong Fenghua Advanced Tech); Manufacturer Part Number: 0402X225M100NT
footprint CAP-0402 (0402 (1005M) Capacitor)
pins: 1, 2

## 0402X225M160NT
designator C?  Capacitance: 2.2uF  (hidden comment: *)
Capacitor, Ceramic (MLCC), 2.2uF, ±20%, 16V, X5R, ±20%, SMD 0402; Manufacturer: FH(Guangdong Fenghua Advanced Tech); Manufacturer Part Number: 0402X225M160NT
footprint CAP-0402 (0402 (1005M) Capacitor)
pins: 1, 2

## 0402X334K6R3CT
designator C?  Capacitance: 330nF  (hidden comment: *)
Capacitor, Ceramic (MLCC), 330nF, ±10%, 6.3V, X5R, ±10%, SMD 0402; Manufacturer: Walsin Tech Corp; Manufacturer Part Number: 0402X334K6R3CT
footprint CAP-0402 (0402 (1005M) Capacitor)
pins: 1, 2

## 0402X334K100CT
designator C?  Capacitance: 330nF  (hidden comment: *)
Capacitor, Ceramic (MLCC), 330nF, ±10%, 10V, X5R, ±10%, SMD 0402; Manufacturer: Walsin Tech Corp; Manufacturer Part Number: 0402X334K100CT
footprint CAP-0402 (0402 (1005M) Capacitor)
pins: 1, 2

## 0402X473K100CT
designator C?  Capacitance: 47nF  (hidden comment: *)
Capacitor, Ceramic (MLCC), 47nF, ±10%, 10V, X5R, ±10%, SMD 0402; Manufacturer: Walsin Tech Corp; Manufacturer Part Number: 0402X473K100CT
footprint CAP-0402 (0402 (1005M) Capacitor)
pins: 1, 2

## 0402X474K6R3CT
designator C?  Capacitance: 470nF  (hidden comment: *)
Capacitor, Ceramic (MLCC), 470nF, ±10%, 6.3V, X5R, ±10%, SMD 0402; Manufacturer: Walsin Tech Corp; Manufacturer Part Number: 0402X474K6R3CT
footprint CAP-0402 (0402 (1005M) Capacitor)
pins: 1, 2

## 0402X474K100CT
designator C?  Capacitance: 470nF  (hidden comment: *)
Capacitor, Ceramic (MLCC), 470nF, ±10%, 10V, X5R, ±10%, SMD 0402; Manufacturer: Walsin Tech Corp; Manufacturer Part Number: 0402X474K100CT
footprint CAP-0402 (0402 (1005M) Capacitor)
pins: 1, 2

## 0402X474K160CT
designator C?  Capacitance: 470nF  (hidden comment: *)
Capacitor, Ceramic (MLCC), 470nF, ±10%, 16V, X5R, ±10%, SMD 0402; Manufacturer: Walsin Tech Corp; Manufacturer Part Number: 0402X474K160CT
footprint CAP-0402 (0402 (1005M) Capacitor)
pins: 1, 2

## 0402X474K250CT
designator C?  Capacitance: 470nF  (hidden comment: *)
Capacitor, Ceramic (MLCC), 470nF, ±10%, 25V, X5R, ±10%, SMD 0402; Manufacturer: Walsin Tech Corp; Manufacturer Part Number: 0402X474K250CT
footprint CAP-0402 (0402 (1005M) Capacitor)
pins: 1, 2

## 0402X474K500CT
designator C?  Capacitance: 470nF  (hidden comment: *)
Capacitor, Ceramic (MLCC), 470nF, ±10%, 50V, X5R, ±10%, SMD 0402; Manufacturer: Walsin Tech Corp; Manufacturer Part Number: 0402X474K500CT
footprint CAP-0402 (0402 (1005M) Capacitor)
pins: 1, 2

## 0402X475K6R3NT
designator C?  Capacitance: 4.7uF  (hidden comment: *)
Capacitor, Ceramic (MLCC), 4.7uF, ±10%, 6.3V, X5R, ±10%, SMD 0402; Manufacturer: FH(Guangdong Fenghua Advanced Tech); Manufacturer Part Number: 0402X475K6R3NT
footprint CAP-0402 (0402 (1005M) Capacitor)
pins: 1, 2

## 0402X475K100NT
designator C?  Capacitance: 4.7uF  (hidden comment: *)
Capacitor, Ceramic (MLCC), 4.7uF, ±10%, 10V, X5R, ±10%, SMD 0402; Manufacturer: FH(Guangdong Fenghua Advanced Tech); Manufacturer Part Number: 0402X475K100NT
footprint CAP-0402 (0402 (1005M) Capacitor)
pins: 1, 2

## 0402X475M6R3CT
designator C?  Capacitance: 4.7uF  (hidden comment: *)
Capacitor, Ceramic (MLCC), 4.7uF, ±20%, 6.3V, X5R, ±20%, SMD 0402; Manufacturer: Walsin Tech Corp; Manufacturer Part Number: 0402X475M6R3CT
footprint CAP-0402 (0402 (1005M) Capacitor)
pins: 1, 2

## 0402X475M6R3NT
designator C?  Capacitance: 4.7uF  (hidden comment: *)
Capacitor, Ceramic (MLCC), 4.7uF, ±20%, 6.3V, X5R, ±20%, SMD 0402; Manufacturer: FH(Guangdong Fenghua Advanced Tech); Manufacturer Part Number: 0402X475M6R3NT
footprint CAP-0402 (0402 (1005M) Capacitor)
pins: 1, 2

## 0402X475M100CT
designator C?  Capacitance: 4.7uF  (hidden comment: *)
Capacitor, Ceramic (MLCC), 4.7uF, ±20%, 10V, X5R, ±20%, SMD 0402; Manufacturer: Walsin Tech Corp; Manufacturer Part Number: 0402X475M100CT
footprint CAP-0402 (0402 (1005M) Capacitor)
pins: 1, 2

## 0402X475M100NT
designator C?  Capacitance: 4.7uF  (hidden comment: *)
Capacitor, Ceramic (MLCC), 4.7uF, ±20%, 10V, X5R, ±20%, SMD 0402; Manufacturer: FH(Guangdong Fenghua Advanced Tech); Manufacturer Part Number: 0402X475M100NT
footprint CAP-0402 (0402 (1005M) Capacitor)
pins: 1, 2

## 0402X684K100CT
designator C?  Capacitance: 680nF  (hidden comment: *)
Capacitor, Ceramic (MLCC), 680nF, ±10%, 10V, X5R, ±10%, SMD 0402; Manufacturer: Walsin Tech Corp; Manufacturer Part Number: 0402X684K100CT
footprint CAP-0402 (0402 (1005M) Capacitor)
pins: 1, 2

## 0402X823K160CT
designator C?  Capacitance: 82nF  (hidden comment: *)
Capacitor, Ceramic (MLCC), 82nF, ±10%, 16V, X5R, ±10%, SMD 0402; Manufacturer: Walsin Tech Corp; Manufacturer Part Number: 0402X823K160CT
footprint CAP-0402 (0402 (1005M) Capacitor)
pins: 1, 2

## 0402YC822KAT2A
designator C?  Capacitance: 8.2nF  (hidden comment: *)
Capacitor, Ceramic (MLCC), 8.2nF, ±10%, 16V, X7R, ±10%, SMD 0402; Manufacturer: AVX; Manufacturer Part Number: 0402YC822KAT2A
footprint CAP-0402 (0402 (1005M) Capacitor)
pins: 1, 2

## 0402YD104KAT2A
designator C?  Capacitance: 100nF  (hidden comment: *)
Capacitor, Ceramic (MLCC), 100nF, ±10%, 16V, X5R, ±10%, SMD 0402; Manufacturer: AVX; Manufacturer Part Number: 0402YD104KAT2A
footprint CAP-0402 (0402 (1005M) Capacitor)
pins: 1, 2

## 0402ZD105KAT2A
designator C?  Capacitance: 1uF  (hidden comment: *)
Capacitor, Ceramic (MLCC), 1uF, ±10%, 10V, X5R, ±10%, SMD 0402; Manufacturer: AVX; Manufacturer Part Number: 0402ZD105KAT2A
footprint CAP-0402 (0402 (1005M) Capacitor)
pins: 1, 2

## 500R07N100JV4T
designator C?  Capacitance: 10pF  (hidden comment: *)
Capacitor, Ceramic (MLCC), 10pF, ±5%, 50V, NP0, ±5%, SMD 0402; Manufacturer: Johanson Dielectrics; Manufacturer Part Number: 500R07N100JV4T
footprint CAP-0402 (0402 (1005M) Capacitor)
pins: 1, 2

## 500R07N101JV4T
designator C?  Capacitance: 100pF  (hidden comment: *)
Capacitor, Ceramic (MLCC), 100pF, ±5%, 50V, NP0, ±5%, SMD 0402; Manufacturer: Johanson Dielectrics; Manufacturer Part Number: 500R07N101JV4T
footprint CAP-0402 (0402 (1005M) Capacitor)
pins: 1, 2

## 500R07N150JV4T
designator C?  Capacitance: 15pF  (hidden comment: *)
Capacitor, Ceramic (MLCC), 15pF, ±5%, 50V, NP0, ±5%, SMD 0402; Manufacturer: Johanson Dielectrics; Manufacturer Part Number: 500R07N150JV4T
footprint CAP-0402 (0402 (1005M) Capacitor)
pins: 1, 2

## 500R07N180JV4T
designator C?  Capacitance: 18pF  (hidden comment: *)
Capacitor, Ceramic (MLCC), 18pF, ±5%, 50V, NP0, ±5%, SMD 0402; Manufacturer: Johanson Dielectrics; Manufacturer Part Number: 500R07N180JV4T
footprint CAP-0402 (0402 (1005M) Capacitor)
pins: 1, 2

## 500R07N220JV4T
designator C?  Capacitance: 22pF  (hidden comment: *)
Capacitor, Ceramic (MLCC), 22pF, ±5%, 50V, NP0, ±5%, SMD 0402; Manufacturer: Johanson Dielectrics; Manufacturer Part Number: 500R07N220JV4T
footprint CAP-0402 (0402 (1005M) Capacitor)
pins: 1, 2

## 500R07N221JV4T
designator C?  Capacitance: 220pF  (hidden comment: *)
Capacitor, Ceramic (MLCC), 220pF, ±5%, 50V, NP0, ±5%, SMD 0402; Manufacturer: Johanson Dielectrics; Manufacturer Part Number: 500R07N221JV4T
footprint CAP-0402 (0402 (1005M) Capacitor)
pins: 1, 2

## 500R07N330JV4T
designator C?  Capacitance: 33pF  (hidden comment: *)
Capacitor, Ceramic (MLCC), 33pF, ±5%, 50V, NP0, ±5%, SMD 0402; Manufacturer: Johanson Dielectrics; Manufacturer Part Number: 500R07N330JV4T
footprint CAP-0402 (0402 (1005M) Capacitor)
pins: 1, 2

## 500R07N680JV4T
designator C?  Capacitance: 68pF  (hidden comment: *)
Capacitor, Ceramic (MLCC), 68pF, ±5%, 50V, NP0, ±5%, SMD 0402; Manufacturer: Johanson Dielectrics; Manufacturer Part Number: 500R07N680JV4T
footprint CAP-0402 (0402 (1005M) Capacitor)
pins: 1, 2

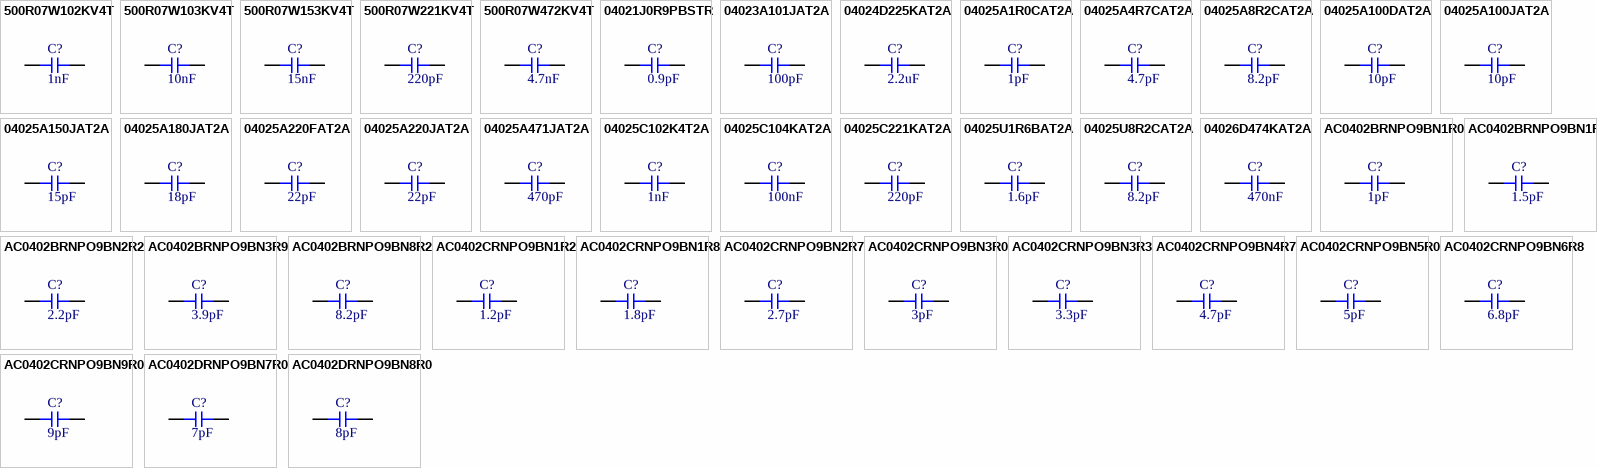
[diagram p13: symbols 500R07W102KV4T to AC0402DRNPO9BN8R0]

## 500R07W102KV4T
designator C?  Capacitance: 1nF  (hidden comment: *)
Capacitor, Ceramic (MLCC), 1nF, ±10%, 50V, X7R, ±10%, SMD 0402; Manufacturer: Johanson Dielectrics; Manufacturer Part Number: 500R07W102KV4T
footprint CAP-0402 (0402 (1005M) Capacitor)
pins: 1, 2

## 500R07W103KV4T
designator C?  Capacitance: 10nF  (hidden comment: *)
Capacitor, Ceramic (MLCC), 10nF, ±10%, 50V, X7R, ±10%, SMD 0402; Manufacturer: Johanson Dielectrics; Manufacturer Part Number: 500R07W103KV4T
footprint CAP-0402 (0402 (1005M) Capacitor)
pins: 1, 2

## 500R07W153KV4T
designator C?  Capacitance: 15nF  (hidden comment: *)
Capacitor, Ceramic (MLCC), 15nF, ±10%, 50V, X7R, ±10%, SMD 0402; Manufacturer: Johanson Dielectrics; Manufacturer Part Number: 500R07W153KV4T
footprint CAP-0402 (0402 (1005M) Capacitor)
pins: 1, 2

## 500R07W221KV4T
designator C?  Capacitance: 220pF  (hidden comment: *)
Capacitor, Ceramic (MLCC), 220pF, ±10%, 50V, X7R, ±10%, SMD 0402; Manufacturer: Johanson Dielectrics; Manufacturer Part Number: 500R07W221KV4T
footprint CAP-0402 (0402 (1005M) Capacitor)
pins: 1, 2

## 500R07W472KV4T
designator C?  Capacitance: 4.7nF  (hidden comment: *)
Capacitor, Ceramic (MLCC), 4.7nF, ±10%, 50V, X7R, ±10%, SMD 0402; Manufacturer: Johanson Dielectrics; Manufacturer Part Number: 500R07W472KV4T
footprint CAP-0402 (0402 (1005M) Capacitor)
pins: 1, 2

## 04021J0R9PBSTR
designator C?  Capacitance: 0.9pF  (hidden comment: *)
Capacitor, Ceramic (MLCC), 0.9pF, ±0.02pF, 100V, ±0.02pF, SMD 0402; Manufacturer: AVX; Manufacturer Part Number: 04021J0R9PBSTR
footprint CAP-0402 (0402 (1005M) Capacitor)
pins: 1, 2

## 04023A101JAT2A
designator C?  Capacitance: 100pF  (hidden comment: *)
Capacitor, Ceramic (MLCC), 100pF, ±5%, 25V, C0G, ±5%, SMD 0402; Manufacturer: AVX; Manufacturer Part Number: 04023A101JAT2A
footprint CAP-0402 (0402 (1005M) Capacitor)
pins: 1, 2

## 04024D225KAT2A
designator C?  Capacitance: 2.2uF  (hidden comment: *)
Capacitor, Ceramic (MLCC), 2.2uF, ±10%, 4V, X5R, ±10%, SMD 0402; Manufacturer: AVX; Manufacturer Part Number: 04024D225KAT2A
footprint CAP-0402 (0402 (1005M) Capacitor)
pins: 1, 2

## 04025A1R0CAT2A
designator C?  Capacitance: 1pF  (hidden comment: *)
Capacitor, Ceramic (MLCC), 1pF, ±0.25pF, 50V, C0G, ±0.25pF, SMD 0402; Manufacturer: AVX; Manufacturer Part Number: 04025A1R0CAT2A
footprint CAP-0402 (0402 (1005M) Capacitor)
pins: 1, 2

## 04025A4R7CAT2A
designator C?  Capacitance: 4.7pF  (hidden comment: *)
Capacitor, Ceramic (MLCC), 4.7pF, ±0.25pF, 50V, C0G, ±0.25pF, SMD 0402; Manufacturer: AVX; Manufacturer Part Number: 04025A4R7CAT2A
footprint CAP-0402 (0402 (1005M) Capacitor)
pins: 1, 2

## 04025A8R2CAT2A
designator C?  Capacitance: 8.2pF  (hidden comment: *)
Capacitor, Ceramic (MLCC), 8.2pF, ±0.25pF, 50V, C0G, ±0.25pF, SMD 0402; Manufacturer: AVX; Manufacturer Part Number: 04025A8R2CAT2A
footprint CAP-0402 (0402 (1005M) Capacitor)
pins: 1, 2

## 04025A100DAT2A
designator C?  Capacitance: 10pF  (hidden comment: *)
Capacitor, Ceramic (MLCC), 10pF, ±0.5pF, 50V, C0G, ±0.5pF, SMD 0402; Manufacturer: AVX; Manufacturer Part Number: 04025A100DAT2A
footprint CAP-0402 (0402 (1005M) Capacitor)
pins: 1, 2

## 04025A100JAT2A
designator C?  Capacitance: 10pF  (hidden comment: *)
Capacitor, Ceramic (MLCC), 10pF, ±5%, 50V, C0G, ±5%, SMD 0402; Manufacturer: AVX; Manufacturer Part Number: 04025A100JAT2A
footprint CAP-0402 (0402 (1005M) Capacitor)
pins: 1, 2

## 04025A150JAT2A
designator C?  Capacitance: 15pF  (hidden comment: *)
Capacitor, Ceramic (MLCC), 15pF, ±5%, 50V, C0G, ±5%, SMD 0402; Manufacturer: AVX; Manufacturer Part Number: 04025A150JAT2A
footprint CAP-0402 (0402 (1005M) Capacitor)
pins: 1, 2

## 04025A180JAT2A
designator C?  Capacitance: 18pF  (hidden comment: *)
Capacitor, Ceramic (MLCC), 18pF, ±5%, 50V, C0G, ±5%, SMD 0402; Manufacturer: AVX; Manufacturer Part Number: 04025A180JAT2A
footprint CAP-0402 (0402 (1005M) Capacitor)
pins: 1, 2

## 04025A220FAT2A
designator C?  Capacitance: 22pF  (hidden comment: *)
Capacitor, Ceramic (MLCC), 22pF, ±1%, 50V, C0G, ±1%, SMD 0402; Manufacturer: AVX; Manufacturer Part Number: 04025A220FAT2A
footprint CAP-0402 (0402 (1005M) Capacitor)
pins: 1, 2

## 04025A220JAT2A
designator C?  Capacitance: 22pF  (hidden comment: *)
Capacitor, Ceramic (MLCC), 22pF, ±5%, 50V, C0G, ±5%, SMD 0402; Manufacturer: AVX; Manufacturer Part Number: 04025A220JAT2A
footprint CAP-0402 (0402 (1005M) Capacitor)
pins: 1, 2

## 04025A471JAT2A
designator C?  Capacitance: 470pF  (hidden comment: *)
Capacitor, Ceramic (MLCC), 470pF, ±5%, 50V, C0G, ±5%, SMD 0402; Manufacturer: AVX; Manufacturer Part Number: 04025A471JAT2A
footprint CAP-0402 (0402 (1005M) Capacitor)
pins: 1, 2

## 04025C102K4T2A
designator C?  Capacitance: 1nF  (hidden comment: *)
Capacitor, Ceramic (MLCC), 1nF, ±10%, 50V, X7R, ±10%, SMD 0402; Manufacturer: AVX; Manufacturer Part Number: 04025C102K4T2A
footprint CAP-0402 (0402 (1005M) Capacitor)
pins: 1, 2

## 04025C104KAT2A
designator C?  Capacitance: 100nF  (hidden comment: *)
Capacitor, Ceramic (MLCC), 100nF, ±10%, 50V, X7R, ±10%, SMD 0402; Manufacturer: Kyocera AVX; Manufacturer Part Number: 04025C104KAT2A
footprint CAP-0402 (0402 (1005M) Capacitor)
pins: 1, 2

## 04025C221KAT2A
designator C?  Capacitance: 220pF  (hidden comment: *)
Capacitor, Ceramic (MLCC), 220pF, ±10%, 50V, X7R, ±10%, SMD 0402; Manufacturer: AVX; Manufacturer Part Number: 04025C221KAT2A
footprint CAP-0402 (0402 (1005M) Capacitor)
pins: 1, 2

## 04025U1R6BAT2A
designator C?  Capacitance: 1.6pF  (hidden comment: *)
Capacitor, Ceramic (MLCC), 1.6pF, ±0.1pF, 50V, C0G, ±0.1pF, SMD 0402; Manufacturer: AVX; Manufacturer Part Number: 04025U1R6BAT2A
footprint CAP-0402 (0402 (1005M) Capacitor)
pins: 1, 2

## 04025U8R2CAT2A
designator C?  Capacitance: 8.2pF  (hidden comment: *)
Capacitor, Ceramic (MLCC), 8.2pF, ±0.25pF, 50V, C0G, ±0.25pF, SMD 0402; Manufacturer: AVX; Manufacturer Part Number: 04025U8R2CAT2A
footprint CAP-0402 (0402 (1005M) Capacitor)
pins: 1, 2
